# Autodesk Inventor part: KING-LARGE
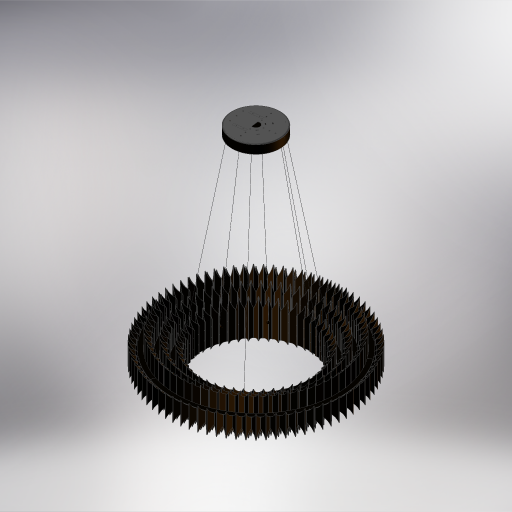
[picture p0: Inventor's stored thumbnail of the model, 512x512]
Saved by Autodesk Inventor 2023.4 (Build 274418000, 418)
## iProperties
Created: 2024-05
Part Number: KING-LARGE
Material: Generic
Document SubType Name: Modeling
Designer: JM
Density: 1 g/cm^3
Appearance: Default
Author: JM
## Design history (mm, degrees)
derived "KING-LARGE-0001-CUSTOMER.iam"
body "Solid1"
node "KINX-0008 - Ring size 4.iam:1::KINX0008.1 - Ring size 4.ipt:"
node "KINX-0020 - Ring size 5.iam:1::KINX-0020.1 - Ring size 5.ipt"
body "Solid2"
node "KINX-0021 - Ring size 6.iam:1::KINX-0021.1 - Ring size 6.ipt"
body "Solid3"
node "KINX-0022 - Ring top cover - size 5 - 959mm dia.ipt:1"
body "Solid4"
node "KINX-0023 - Ring top cover - size 6 - 1107mm dia.ipt:1"
body "Solid5"
node "KINX-0011 - Ring top cover - size 4 - 811mm dia.ipt:1"
body "Solid6"
node "KINX-0023 - Ring top cover - size 6 - 1107mm dia.ipt:2"
body "Solid7"
node "KINX-0022 - Ring top cover - size 5 - 959mm dia.ipt:2"
body "Solid8"
node "KINX-0011 - Ring top cover - size 4 - 811mm dia.ipt:2"
body "Solid9"
node "KINX-0023 - Ring top cover - size 6 - 1107mm dia.ipt:3"
body "Solid10"
node "KINX-0022 - Ring top cover - size 5 - 959mm dia.ipt:3"
body "Solid11"
node "KINX-0011 - Ring top cover - size 4 - 811mm dia.ipt:3"
body "Solid12"
node "KINX-0023 - Ring top cover - size 6 - 1107mm dia.ipt:4"
body "Solid13"
node "KINX-0022 - Ring top cover - size 5 - 959mm dia.ipt:4"
body "Solid14"
node "KINX-0011 - Ring top cover - size 4 - 811mm dia.ipt:4"
body "Solid15"
node "KINX-0023 - Ring top cover - size 6 - 1107mm dia.ipt:5"
body "Solid16"
node "KINX-0022 - Ring top cover - size 5 - 959mm dia.ipt:5"
body "Solid17"
node "KINX-0011 - Ring top cover - size 4 - 811mm dia.ipt:5"
body "Solid18"
node "KINX-0005 (KNG-UNILF-03) - Short outer leaves - CUSTOMERCAD."
body "Solid19"
node "KINX-0003 (KNG-UNILF-01) - Middle leaves - CUSTOMERCAD.ipt:1"
body "Solid20"
node "KINX-0001 (KNG-UNILF-02) - Inner leaves - CUSTOMERCAD.ipt:1"
body "Solid21"
node "KINX-0005 (KNG-UNILF-03) - Short outer leaves - CUSTOMERCAD."
body "Solid22"
node "KINX-0005 (KNG-UNILF-03) - Short outer leaves - CUSTOMERCAD."
body "Solid23"
node "KINX-0005 (KNG-UNILF-03) - Short outer leaves - CUSTOMERCAD."
body "Solid24"
node "KINX-0005 (KNG-UNILF-03) - Short outer leaves - CUSTOMERCAD."
body "Solid25"
node "KINX-0005 (KNG-UNILF-03) - Short outer leaves - CUSTOMERCAD."
body "Solid26"
node "KINX-0005 (KNG-UNILF-03) - Short outer leaves - CUSTOMERCAD."
body "Solid27"
node "KINX-0005 (KNG-UNILF-03) - Short outer leaves - CUSTOMERCAD."
body "Solid28"
node "KINX-0005 (KNG-UNILF-03) - Short outer leaves - CUSTOMERCAD."
body "Solid29"
node "KINX-0005 (KNG-UNILF-03) - Short outer leaves - CUSTOMERCAD."
body "Solid30"
node "KINX-0005 (KNG-UNILF-03) - Short outer leaves - CUSTOMERCAD."
body "Solid31"
node "KINX-0005 (KNG-UNILF-03) - Short outer leaves - CUSTOMERCAD."
body "Solid32"
node "KINX-0005 (KNG-UNILF-03) - Short outer leaves - CUSTOMERCAD."
body "Solid33"
node "KINX-0005 (KNG-UNILF-03) - Short outer leaves - CUSTOMERCAD."
body "Solid34"
node "KINX-0005 (KNG-UNILF-03) - Short outer leaves - CUSTOMERCAD."
body "Solid35"
node "KINX-0005 (KNG-UNILF-03) - Short outer leaves - CUSTOMERCAD."
body "Solid36"
node "KINX-0005 (KNG-UNILF-03) - Short outer leaves - CUSTOMERCAD."
body "Solid37"
node "KINX-0005 (KNG-UNILF-03) - Short outer leaves - CUSTOMERCAD."
body "Solid38"
node "KINX-0005 (KNG-UNILF-03) - Short outer leaves - CUSTOMERCAD."
body "Solid39"
node "KINX-0005 (KNG-UNILF-03) - Short outer leaves - CUSTOMERCAD."
body "Solid40"
node "KINX-0005 (KNG-UNILF-03) - Short outer leaves - CUSTOMERCAD."
body "Solid41"
node "KINX-0005 (KNG-UNILF-03) - Short outer leaves - CUSTOMERCAD."
body "Solid42"
node "KINX-0005 (KNG-UNILF-03) - Short outer leaves - CUSTOMERCAD."
body "Solid43"
node "KINX-0005 (KNG-UNILF-03) - Short outer leaves - CUSTOMERCAD."
body "Solid44"
node "KINX-0005 (KNG-UNILF-03) - Short outer leaves - CUSTOMERCAD."
body "Solid45"
node "KINX-0005 (KNG-UNILF-03) - Short outer leaves - CUSTOMERCAD."
body "Solid46"
node "KINX-0005 (KNG-UNILF-03) - Short outer leaves - CUSTOMERCAD."
body "Solid47"
node "KINX-0005 (KNG-UNILF-03) - Short outer leaves - CUSTOMERCAD."
body "Solid48"
node "KINX-0005 (KNG-UNILF-03) - Short outer leaves - CUSTOMERCAD."
body "Solid49"
node "KINX-0005 (KNG-UNILF-03) - Short outer leaves - CUSTOMERCAD."
body "Solid50"
node "KINX-0005 (KNG-UNILF-03) - Short outer leaves - CUSTOMERCAD."
body "Solid51"
node "KINX-0005 (KNG-UNILF-03) - Short outer leaves - CUSTOMERCAD."
body "Solid52"
node "KINX-0005 (KNG-UNILF-03) - Short outer leaves - CUSTOMERCAD."
body "Solid53"
node "KINX-0005 (KNG-UNILF-03) - Short outer leaves - CUSTOMERCAD."
body "Solid54"
node "KINX-0005 (KNG-UNILF-03) - Short outer leaves - CUSTOMERCAD."
body "Solid55"
node "KINX-0005 (KNG-UNILF-03) - Short outer leaves - CUSTOMERCAD."
body "Solid56"
node "KINX-0005 (KNG-UNILF-03) - Short outer leaves - CUSTOMERCAD."
body "Solid57"
node "KINX-0005 (KNG-UNILF-03) - Short outer leaves - CUSTOMERCAD."
body "Solid58"
node "KINX-0005 (KNG-UNILF-03) - Short outer leaves - CUSTOMERCAD."
body "Solid59"
node "KINX-0005 (KNG-UNILF-03) - Short outer leaves - CUSTOMERCAD."
body "Solid60"
node "KINX-0005 (KNG-UNILF-03) - Short outer leaves - CUSTOMERCAD."
body "Solid61"
node "KINX-0005 (KNG-UNILF-03) - Short outer leaves - CUSTOMERCAD."
body "Solid62"
node "KINX-0005 (KNG-UNILF-03) - Short outer leaves - CUSTOMERCAD."
body "Solid63"
node "KINX-0005 (KNG-UNILF-03) - Short outer leaves - CUSTOMERCAD."
body "Solid64"
node "KINX-0005 (KNG-UNILF-03) - Short outer leaves - CUSTOMERCAD."
body "Solid65"
node "KINX-0005 (KNG-UNILF-03) - Short outer leaves - CUSTOMERCAD."
body "Solid66"
node "KINX-0005 (KNG-UNILF-03) - Short outer leaves - CUSTOMERCAD."
body "Solid67"
node "KINX-0005 (KNG-UNILF-03) - Short outer leaves - CUSTOMERCAD."
body "Solid68"
node "KINX-0005 (KNG-UNILF-03) - Short outer leaves - CUSTOMERCAD."
body "Solid69"
node "KINX-0005 (KNG-UNILF-03) - Short outer leaves - CUSTOMERCAD."
body "Solid70"
node "KINX-0005 (KNG-UNILF-03) - Short outer leaves - CUSTOMERCAD."
body "Solid71"
node "KINX-0005 (KNG-UNILF-03) - Short outer leaves - CUSTOMERCAD."
body "Solid72"
node "KINX-0005 (KNG-UNILF-03) - Short outer leaves - CUSTOMERCAD."
body "Solid73"
node "KINX-0005 (KNG-UNILF-03) - Short outer leaves - CUSTOMERCAD."
body "Solid74"
node "KINX-0005 (KNG-UNILF-03) - Short outer leaves - CUSTOMERCAD."
body "Solid75"
node "KINX-0005 (KNG-UNILF-03) - Short outer leaves - CUSTOMERCAD."
body "Solid76"
node "KINX-0005 (KNG-UNILF-03) - Short outer leaves - CUSTOMERCAD."
body "Solid77"
node "KINX-0005 (KNG-UNILF-03) - Short outer leaves - CUSTOMERCAD."
body "Solid78"
node "KINX-0005 (KNG-UNILF-03) - Short outer leaves - CUSTOMERCAD."
body "Solid79"
node "KINX-0005 (KNG-UNILF-03) - Short outer leaves - CUSTOMERCAD."
body "Solid80"
node "KINX-0005 (KNG-UNILF-03) - Short outer leaves - CUSTOMERCAD."
body "Solid81"
node "KINX-0005 (KNG-UNILF-03) - Short outer leaves - CUSTOMERCAD."
body "Solid82"
node "KINX-0005 (KNG-UNILF-03) - Short outer leaves - CUSTOMERCAD."
body "Solid83"
node "KINX-0005 (KNG-UNILF-03) - Short outer leaves - CUSTOMERCAD."
body "Solid84"
node "KINX-0005 (KNG-UNILF-03) - Short outer leaves - CUSTOMERCAD."
body "Solid85"
node "KINX-0005 (KNG-UNILF-03) - Short outer leaves - CUSTOMERCAD."
body "Solid86"
node "KINX-0005 (KNG-UNILF-03) - Short outer leaves - CUSTOMERCAD."
body "Solid87"
node "KINX-0005 (KNG-UNILF-03) - Short outer leaves - CUSTOMERCAD."
body "Solid88"
node "KINX-0005 (KNG-UNILF-03) - Short outer leaves - CUSTOMERCAD."
body "Solid89"
node "KINX-0005 (KNG-UNILF-03) - Short outer leaves - CUSTOMERCAD."
body "Solid90"
node "KINX-0005 (KNG-UNILF-03) - Short outer leaves - CUSTOMERCAD."
body "Solid91"
node "KINX-0005 (KNG-UNILF-03) - Short outer leaves - CUSTOMERCAD."
body "Solid92"
node "KINX-0005 (KNG-UNILF-03) - Short outer leaves - CUSTOMERCAD."
body "Solid93"
node "KINX-0005 (KNG-UNILF-03) - Short outer leaves - CUSTOMERCAD."
body "Solid94"
node "KINX-0005 (KNG-UNILF-03) - Short outer leaves - CUSTOMERCAD."
body "Solid95"
node "KINX-0005 (KNG-UNILF-03) - Short outer leaves - CUSTOMERCAD."
body "Solid96"
node "KINX-0005 (KNG-UNILF-03) - Short outer leaves - CUSTOMERCAD."
body "Solid97"
node "KINX-0005 (KNG-UNILF-03) - Short outer leaves - CUSTOMERCAD."
body "Solid98"
node "KINX-0005 (KNG-UNILF-03) - Short outer leaves - CUSTOMERCAD."
body "Solid99"
node "KINX-0005 (KNG-UNILF-03) - Short outer leaves - CUSTOMERCAD."
body "Solid100"
node "KINX-0003 (KNG-UNILF-01) - Middle leaves - CUSTOMERCAD.ipt:2"
body "Solid101"
node "KINX-0003 (KNG-UNILF-01) - Middle leaves - CUSTOMERCAD.ipt:3"
body "Solid102"
node "KINX-0003 (KNG-UNILF-01) - Middle leaves - CUSTOMERCAD.ipt:4"
body "Solid103"
node "KINX-0003 (KNG-UNILF-01) - Middle leaves - CUSTOMERCAD.ipt:5"
body "Solid104"
node "KINX-0003 (KNG-UNILF-01) - Middle leaves - CUSTOMERCAD.ipt:6"
body "Solid105"
node "KINX-0003 (KNG-UNILF-01) - Middle leaves - CUSTOMERCAD.ipt:7"
body "Solid106"
node "KINX-0003 (KNG-UNILF-01) - Middle leaves - CUSTOMERCAD.ipt:8"
body "Solid107"
node "KINX-0003 (KNG-UNILF-01) - Middle leaves - CUSTOMERCAD.ipt:9"
body "Solid108"
node "KINX-0003 (KNG-UNILF-01) - Middle leaves - CUSTOMERCAD.ipt:1"
body "Solid109"
node "KINX-0003 (KNG-UNILF-01) - Middle leaves - CUSTOMERCAD.ipt:1"
body "Solid110"
node "KINX-0003 (KNG-UNILF-01) - Middle leaves - CUSTOMERCAD.ipt:1"
body "Solid111"
node "KINX-0003 (KNG-UNILF-01) - Middle leaves - CUSTOMERCAD.ipt:1"
body "Solid112"
node "KINX-0003 (KNG-UNILF-01) - Middle leaves - CUSTOMERCAD.ipt:1"
body "Solid113"
node "KINX-0003 (KNG-UNILF-01) - Middle leaves - CUSTOMERCAD.ipt:1"
body "Solid114"
node "KINX-0003 (KNG-UNILF-01) - Middle leaves - CUSTOMERCAD.ipt:1"
body "Solid115"
node "KINX-0003 (KNG-UNILF-01) - Middle leaves - CUSTOMERCAD.ipt:1"
body "Solid116"
node "KINX-0003 (KNG-UNILF-01) - Middle leaves - CUSTOMERCAD.ipt:1"
body "Solid117"
node "KINX-0003 (KNG-UNILF-01) - Middle leaves - CUSTOMERCAD.ipt:1"
body "Solid118"
node "KINX-0003 (KNG-UNILF-01) - Middle leaves - CUSTOMERCAD.ipt:2"
body "Solid119"
node "KINX-0003 (KNG-UNILF-01) - Middle leaves - CUSTOMERCAD.ipt:2"
body "Solid120"
node "KINX-0003 (KNG-UNILF-01) - Middle leaves - CUSTOMERCAD.ipt:2"
body "Solid121"
node "KINX-0003 (KNG-UNILF-01) - Middle leaves - CUSTOMERCAD.ipt:2"
body "Solid122"
node "KINX-0003 (KNG-UNILF-01) - Middle leaves - CUSTOMERCAD.ipt:2"
body "Solid123"
node "KINX-0003 (KNG-UNILF-01) - Middle leaves - CUSTOMERCAD.ipt:2"
body "Solid124"
node "KINX-0003 (KNG-UNILF-01) - Middle leaves - CUSTOMERCAD.ipt:2"
body "Solid125"
node "KINX-0003 (KNG-UNILF-01) - Middle leaves - CUSTOMERCAD.ipt:2"
body "Solid126"
node "KINX-0003 (KNG-UNILF-01) - Middle leaves - CUSTOMERCAD.ipt:2"
body "Solid127"
node "KINX-0003 (KNG-UNILF-01) - Middle leaves - CUSTOMERCAD.ipt:2"
body "Solid128"
node "KINX-0003 (KNG-UNILF-01) - Middle leaves - CUSTOMERCAD.ipt:3"
body "Solid129"
node "KINX-0003 (KNG-UNILF-01) - Middle leaves - CUSTOMERCAD.ipt:3"
body "Solid130"
node "KINX-0003 (KNG-UNILF-01) - Middle leaves - CUSTOMERCAD.ipt:3"
body "Solid131"
node "KINX-0003 (KNG-UNILF-01) - Middle leaves - CUSTOMERCAD.ipt:3"
body "Solid132"
node "KINX-0003 (KNG-UNILF-01) - Middle leaves - CUSTOMERCAD.ipt:3"
body "Solid133"
node "KINX-0003 (KNG-UNILF-01) - Middle leaves - CUSTOMERCAD.ipt:3"
body "Solid134"
node "KINX-0003 (KNG-UNILF-01) - Middle leaves - CUSTOMERCAD.ipt:3"
body "Solid135"
node "KINX-0003 (KNG-UNILF-01) - Middle leaves - CUSTOMERCAD.ipt:3"
body "Solid136"
node "KINX-0003 (KNG-UNILF-01) - Middle leaves - CUSTOMERCAD.ipt:3"
body "Solid137"
node "KINX-0003 (KNG-UNILF-01) - Middle leaves - CUSTOMERCAD.ipt:3"
body "Solid138"
node "KINX-0003 (KNG-UNILF-01) - Middle leaves - CUSTOMERCAD.ipt:4"
body "Solid139"
node "KINX-0003 (KNG-UNILF-01) - Middle leaves - CUSTOMERCAD.ipt:4"
body "Solid140"
node "KINX-0003 (KNG-UNILF-01) - Middle leaves - CUSTOMERCAD.ipt:4"
body "Solid141"
node "KINX-0003 (KNG-UNILF-01) - Middle leaves - CUSTOMERCAD.ipt:4"
body "Solid142"
node "KINX-0003 (KNG-UNILF-01) - Middle leaves - CUSTOMERCAD.ipt:4"
body "Solid143"
node "KINX-0003 (KNG-UNILF-01) - Middle leaves - CUSTOMERCAD.ipt:4"
body "Solid144"
node "KINX-0003 (KNG-UNILF-01) - Middle leaves - CUSTOMERCAD.ipt:4"
body "Solid145"
node "KINX-0003 (KNG-UNILF-01) - Middle leaves - CUSTOMERCAD.ipt:4"
body "Solid146"
node "KINX-0003 (KNG-UNILF-01) - Middle leaves - CUSTOMERCAD.ipt:4"
body "Solid147"
node "KINX-0003 (KNG-UNILF-01) - Middle leaves - CUSTOMERCAD.ipt:4"
body "Solid148"
node "KINX-0003 (KNG-UNILF-01) - Middle leaves - CUSTOMERCAD.ipt:5"
body "Solid149"
node "KINX-0003 (KNG-UNILF-01) - Middle leaves - CUSTOMERCAD.ipt:5"
body "Solid150"
node "KINX-0003 (KNG-UNILF-01) - Middle leaves - CUSTOMERCAD.ipt:5"
body "Solid151"
node "KINX-0003 (KNG-UNILF-01) - Middle leaves - CUSTOMERCAD.ipt:5"
body "Solid152"
node "KINX-0003 (KNG-UNILF-01) - Middle leaves - CUSTOMERCAD.ipt:5"
body "Solid153"
node "KINX-0003 (KNG-UNILF-01) - Middle leaves - CUSTOMERCAD.ipt:5"
body "Solid154"
node "KINX-0003 (KNG-UNILF-01) - Middle leaves - CUSTOMERCAD.ipt:5"
body "Solid155"
node "KINX-0003 (KNG-UNILF-01) - Middle leaves - CUSTOMERCAD.ipt:5"
body "Solid156"
node "KINX-0003 (KNG-UNILF-01) - Middle leaves - CUSTOMERCAD.ipt:5"
body "Solid157"
node "KINX-0003 (KNG-UNILF-01) - Middle leaves - CUSTOMERCAD.ipt:5"
body "Solid158"
node "KINX-0003 (KNG-UNILF-01) - Middle leaves - CUSTOMERCAD.ipt:6"
body "Solid159"
node "KINX-0003 (KNG-UNILF-01) - Middle leaves - CUSTOMERCAD.ipt:6"
body "Solid160"
node "KINX-0003 (KNG-UNILF-01) - Middle leaves - CUSTOMERCAD.ipt:6"
body "Solid161"
node "KINX-0003 (KNG-UNILF-01) - Middle leaves - CUSTOMERCAD.ipt:6"
body "Solid162"
node "KINX-0003 (KNG-UNILF-01) - Middle leaves - CUSTOMERCAD.ipt:6"
body "Solid163"
node "KINX-0003 (KNG-UNILF-01) - Middle leaves - CUSTOMERCAD.ipt:6"
body "Solid164"
node "KINX-0003 (KNG-UNILF-01) - Middle leaves - CUSTOMERCAD.ipt:6"
body "Solid165"
node "KINX-0003 (KNG-UNILF-01) - Middle leaves - CUSTOMERCAD.ipt:6"
body "Solid166"
node "KINX-0003 (KNG-UNILF-01) - Middle leaves - CUSTOMERCAD.ipt:6"
body "Solid167"
node "KINX-0003 (KNG-UNILF-01) - Middle leaves - CUSTOMERCAD.ipt:6"
body "Solid168"
node "KINX-0003 (KNG-UNILF-01) - Middle leaves - CUSTOMERCAD.ipt:7"
body "Solid169"
node "KINX-0003 (KNG-UNILF-01) - Middle leaves - CUSTOMERCAD INNER"
body "Solid170"
node "KINX-0003 (KNG-UNILF-01) - Middle leaves - CUSTOMERCAD INNER"
body "Solid171"
node "KINX-0003 (KNG-UNILF-01) - Middle leaves - CUSTOMERCAD INNER"
body "Solid172"
node "KINX-0003 (KNG-UNILF-01) - Middle leaves - CUSTOMERCAD INNER"
body "Solid173"
node "KINX-0003 (KNG-UNILF-01) - Middle leaves - CUSTOMERCAD INNER"
body "Solid174"
node "KINX-0003 (KNG-UNILF-01) - Middle leaves - CUSTOMERCAD INNER"
body "Solid175"
node "KINX-0003 (KNG-UNILF-01) - Middle leaves - CUSTOMERCAD INNER"
body "Solid176"
node "KINX-0003 (KNG-UNILF-01) - Middle leaves - CUSTOMERCAD INNER"
body "Solid177"
node "KINX-0003 (KNG-UNILF-01) - Middle leaves - CUSTOMERCAD INNER"
body "Solid178"
node "KINX-0003 (KNG-UNILF-01) - Middle leaves - CUSTOMERCAD INNER"
body "Solid179"
node "KINX-0003 (KNG-UNILF-01) - Middle leaves - CUSTOMERCAD INNER"
body "Solid180"
node "KINX-0003 (KNG-UNILF-01) - Middle leaves - CUSTOMERCAD INNER"
body "Solid181"
node "KINX-0003 (KNG-UNILF-01) - Middle leaves - CUSTOMERCAD INNER"
body "Solid182"
node "KINX-0003 (KNG-UNILF-01) - Middle leaves - CUSTOMERCAD INNER"
body "Solid183"
node "KINX-0003 (KNG-UNILF-01) - Middle leaves - CUSTOMERCAD INNER"
body "Solid184"
node "KINX-0003 (KNG-UNILF-01) - Middle leaves - CUSTOMERCAD INNER"
body "Solid185"
node "KINX-0003 (KNG-UNILF-01) - Middle leaves - CUSTOMERCAD INNER"
body "Solid186"
node "KINX-0003 (KNG-UNILF-01) - Middle leaves - CUSTOMERCAD INNER"
body "Solid187"
node "KINX-0003 (KNG-UNILF-01) - Middle leaves - CUSTOMERCAD INNER"
body "Solid188"
node "KINX-0003 (KNG-UNILF-01) - Middle leaves - CUSTOMERCAD INNER"
body "Solid189"
node "KINX-0003 (KNG-UNILF-01) - Middle leaves - CUSTOMERCAD INNER"
body "Solid190"
node "KINX-0003 (KNG-UNILF-01) - Middle leaves - CUSTOMERCAD INNER"
body "Solid191"
node "KINX-0003 (KNG-UNILF-01) - Middle leaves - CUSTOMERCAD INNER"
body "Solid192"
node "KINX-0003 (KNG-UNILF-01) - Middle leaves - CUSTOMERCAD INNER"
body "Solid193"
node "KINX-0003 (KNG-UNILF-01) - Middle leaves - CUSTOMERCAD INNER"
body "Solid194"
node "KINX-0003 (KNG-UNILF-01) - Middle leaves - CUSTOMERCAD INNER"
body "Solid195"
node "KINX-0003 (KNG-UNILF-01) - Middle leaves - CUSTOMERCAD INNER"
body "Solid196"
node "KINX-0003 (KNG-UNILF-01) - Middle leaves - CUSTOMERCAD INNER"
body "Solid197"
node "KINX-0003 (KNG-UNILF-01) - Middle leaves - CUSTOMERCAD INNER"
body "Solid198"
node "KINX-0003 (KNG-UNILF-01) - Middle leaves - CUSTOMERCAD INNER"
body "Solid199"
node "KINX-0003 (KNG-UNILF-01) - Middle leaves - CUSTOMERCAD INNER"
body "Solid200"
node "KINX-0003 (KNG-UNILF-01) - Middle leaves - CUSTOMERCAD INNER"
body "Solid201"
node "KINX-0003 (KNG-UNILF-01) - Middle leaves - CUSTOMERCAD INNER"
body "Solid202"
node "KINX-0003 (KNG-UNILF-01) - Middle leaves - CUSTOMERCAD INNER"
body "Solid203"
node "KINX-0003 (KNG-UNILF-01) - Middle leaves - CUSTOMERCAD INNER"
body "Solid204"
node "KINX-0003 (KNG-UNILF-01) - Middle leaves - CUSTOMERCAD INNER"
body "Solid205"
node "KINX-0003 (KNG-UNILF-01) - Middle leaves - CUSTOMERCAD INNER"
body "Solid206"
node "KINX-0003 (KNG-UNILF-01) - Middle leaves - CUSTOMERCAD INNER"
body "Solid207"
node "KINX-0003 (KNG-UNILF-01) - Middle leaves - CUSTOMERCAD INNER"
body "Solid208"
node "KINX-0003 (KNG-UNILF-01) - Middle leaves - CUSTOMERCAD INNER"
body "Solid209"
node "KINX-0003 (KNG-UNILF-01) - Middle leaves - CUSTOMERCAD INNER"
body "Solid210"
node "KINX-0003 (KNG-UNILF-01) - Middle leaves - CUSTOMERCAD INNER"
body "Solid211"
node "KINX-0003 (KNG-UNILF-01) - Middle leaves - CUSTOMERCAD INNER"
body "Solid212"
node "KINX-0003 (KNG-UNILF-01) - Middle leaves - CUSTOMERCAD INNER"
body "Solid213"
node "KINX-0003 (KNG-UNILF-01) - Middle leaves - CUSTOMERCAD INNER"
body "Solid214"
node "KINX-0003 (KNG-UNILF-01) - Middle leaves - CUSTOMERCAD INNER"
body "Solid215"
node "KINX-0003 (KNG-UNILF-01) - Middle leaves - CUSTOMERCAD INNER"
body "Solid216"
node "KINX-0003 (KNG-UNILF-01) - Middle leaves - CUSTOMERCAD INNER"
body "Solid217"
node "KINX-0003 (KNG-UNILF-01) - Middle leaves - CUSTOMERCAD INNER"
body "Solid218"
node "KINX-0003 (KNG-UNILF-01) - Middle leaves - CUSTOMERCAD INNER"
body "Solid219"
node "KINX-0003 (KNG-UNILF-01) - Middle leaves - CUSTOMERCAD INNER"
body "Solid220"
node "KINX-0003 (KNG-UNILF-01) - Middle leaves - CUSTOMERCAD INNER"
body "Solid221"
node "KINX-0003 (KNG-UNILF-01) - Middle leaves - CUSTOMERCAD INNER"
body "Solid222"
node "KINX-0003 (KNG-UNILF-01) - Middle leaves - CUSTOMERCAD INNER"
body "Solid223"
node "KINX-0003 (KNG-UNILF-01) - Middle leaves - CUSTOMERCAD INNER"
body "Solid224"
node "KINX-0003 (KNG-UNILF-01) - Middle leaves - CUSTOMERCAD INNER"
body "Solid225"
node "KINX-0003 (KNG-UNILF-01) - Middle leaves - CUSTOMERCAD INNER"
body "Solid226"
node "KINX-0003 (KNG-UNILF-01) - Middle leaves - CUSTOMERCAD INNER"
body "Solid227"
node "KINX-0003 (KNG-UNILF-01) - Middle leaves - CUSTOMERCAD INNER"
body "Solid228"
node "KINX-0003 (KNG-UNILF-01) - Middle leaves - CUSTOMERCAD INNER"
body "Solid229"
node "KINX-0001 (KNG-UNILF-02) - Inner leaves - CUSTOMERCAD.ipt:2"
body "Solid230"
node "KINX-0001 (KNG-UNILF-02) - Inner leaves - CUSTOMERCAD.ipt:3"
body "Solid231"
node "KINX-0001 (KNG-UNILF-02) - Inner leaves - CUSTOMERCAD.ipt:4"
body "Solid232"
node "KINX-0001 (KNG-UNILF-02) - Inner leaves - CUSTOMERCAD.ipt:5"
body "Solid233"
node "KINX-0001 (KNG-UNILF-02) - Inner leaves - CUSTOMERCAD.ipt:6"
body "Solid234"
node "KINX-0001 (KNG-UNILF-02) - Inner leaves - CUSTOMERCAD.ipt:7"
body "Solid235"
node "KINX-0001 (KNG-UNILF-02) - Inner leaves - CUSTOMERCAD.ipt:8"
body "Solid236"
node "KINX-0001 (KNG-UNILF-02) - Inner leaves - CUSTOMERCAD.ipt:9"
body "Solid237"
node "KINX-0001 (KNG-UNILF-02) - Inner leaves - CUSTOMERCAD.ipt:10"
body "Solid238"
node "KINX-0001 (KNG-UNILF-02) - Inner leaves - CUSTOMERCAD.ipt:11"
body "Solid239"
node "KINX-0001 (KNG-UNILF-02) - Inner leaves - CUSTOMERCAD.ipt:12"
body "Solid240"
node "KINX-0001 (KNG-UNILF-02) - Inner leaves - CUSTOMERCAD.ipt:13"
body "Solid241"
node "KINX-0001 (KNG-UNILF-02) - Inner leaves - CUSTOMERCAD.ipt:14"
body "Solid242"
node "KINX-0001 (KNG-UNILF-02) - Inner leaves - CUSTOMERCAD.ipt:15"
body "Solid243"
node "KINX-0001 (KNG-UNILF-02) - Inner leaves - CUSTOMERCAD.ipt:16"
body "Solid244"
node "KINX-0001 (KNG-UNILF-02) - Inner leaves - CUSTOMERCAD.ipt:17"
body "Solid245"
node "KINX-0001 (KNG-UNILF-02) - Inner leaves - CUSTOMERCAD.ipt:18"
body "Solid246"
node "KINX-0001 (KNG-UNILF-02) - Inner leaves - CUSTOMERCAD.ipt:19"
body "Solid247"
node "KINX-0001 (KNG-UNILF-02) - Inner leaves - CUSTOMERCAD.ipt:20"
body "Solid248"
node "KINX-0001 (KNG-UNILF-02) - Inner leaves - CUSTOMERCAD.ipt:21"
body "Solid249"
node "KINX-0001 (KNG-UNILF-02) - Inner leaves - CUSTOMERCAD.ipt:22"
body "Solid250"
node "KINX-0001 (KNG-UNILF-02) - Inner leaves - CUSTOMERCAD.ipt:23"
body "Solid251"
node "KINX-0001 (KNG-UNILF-02) - Inner leaves - CUSTOMERCAD.ipt:24"
body "Solid252"
node "KINX-0001 (KNG-UNILF-02) - Inner leaves - CUSTOMERCAD.ipt:25"
body "Solid253"
node "KINX-0001 (KNG-UNILF-02) - Inner leaves - CUSTOMERCAD.ipt:26"
body "Solid254"
node "KINX-0001 (KNG-UNILF-02) - Inner leaves - CUSTOMERCAD.ipt:27"
body "Solid255"
node "KINX-0001 (KNG-UNILF-02) - Inner leaves - CUSTOMERCAD.ipt:28"
body "Solid256"
node "KINX-0001 (KNG-UNILF-02) - Inner leaves - CUSTOMERCAD.ipt:29"
body "Solid257"
node "KINX-0001 (KNG-UNILF-02) - Inner leaves - CUSTOMERCAD.ipt:30"
body "Solid258"
node "KINX-0001 (KNG-UNILF-02) - Inner leaves - CUSTOMERCAD.ipt:31"
body "Solid259"
node "KINX-0001 (KNG-UNILF-02) - Inner leaves - CUSTOMERCAD.ipt:32"
body "Solid260"
node "KINX-0001 (KNG-UNILF-02) - Inner leaves - CUSTOMERCAD.ipt:33"
body "Solid261"
node "KINX-0001 (KNG-UNILF-02) - Inner leaves - CUSTOMERCAD.ipt:34"
body "Solid262"
node "KINX-0001 (KNG-UNILF-02) - Inner leaves - CUSTOMERCAD.ipt:35"
body "Solid263"
node "KINX-0001 (KNG-UNILF-02) - Inner leaves - CUSTOMERCAD.ipt:36"
body "Solid264"
node "KINX-0001 (KNG-UNILF-02) - Inner leaves - CUSTOMERCAD.ipt:37"
body "Solid265"
node "KINX-0001 (KNG-UNILF-02) - Inner leaves - CUSTOMERCAD.ipt:38"
body "Solid266"
node "KINX-0001 (KNG-UNILF-02) - Inner leaves - CUSTOMERCAD.ipt:39"
body "Solid267"
node "KINX-0001 (KNG-UNILF-02) - Inner leaves - CUSTOMERCAD.ipt:40"
body "Solid268"
node "KINX-0001 (KNG-UNILF-02) - Inner leaves - CUSTOMERCAD.ipt:41"
body "Solid269"
node "KINX-0001 (KNG-UNILF-02) - Inner leaves - CUSTOMERCAD.ipt:42"
body "Solid270"
node "KINX-0001 (KNG-UNILF-02) - Inner leaves - CUSTOMERCAD.ipt:43"
body "Solid271"
node "KINX-0001 (KNG-UNILF-02) - Inner leaves - CUSTOMERCAD.ipt:44"
body "Solid272"
node "KINX-0001 (KNG-UNILF-02) - Inner leaves - CUSTOMERCAD.ipt:45"
body "Solid273"
node "KINX-0001 (KNG-UNILF-02) - Inner leaves - CUSTOMERCAD.ipt:46"
body "Solid274"
node "KINX-0001 (KNG-UNILF-02) - Inner leaves - CUSTOMERCAD.ipt:47"
body "Solid275"
node "KINX-0001 (KNG-UNILF-02) - Inner leaves - CUSTOMERCAD.ipt:48"
body "Solid276"
node "KINX-0001 (KNG-UNILF-02) - Inner leaves - CUSTOMERCAD.ipt:49"
body "Solid277"
node "KINX-0001 (KNG-UNILF-02) - Inner leaves - CUSTOMERCAD.ipt:50"
body "Solid278"
node "finial-15mm.ipt:1"
body "Solid279"
node "turned-screw-cover.ipt:1"
body "Solid280"
node "turned-screw-cover.ipt:2"
body "Solid281"
node "finial-15mm.ipt:2"
body "Solid282"
node "turned-screw-cover.ipt:3"
body "Solid283"
node "finial-15mm.ipt:3"
body "Solid284"
node "turned-screw-cover.ipt:4"
body "Solid285"
node "finial-15mm.ipt:4"
body "Solid286"
node "turned-screw-cover.ipt:5"
body "Solid287"
node "finial-15mm.ipt:5"
body "Solid288"
node "turned-screw-cover.ipt:6"
body "Solid289"
node "finial-15mm.ipt:6"
body "Solid290"
node "turned-screw-cover.ipt:7"
body "Solid291"
node "finial-15mm.ipt:7"
body "Solid292"
node "turned-screw-cover.ipt:8"
body "Solid293"
node "finial-15mm.ipt:8"
body "Solid294"
node "turned-screw-cover.ipt:9"
body "Solid295"
node "finial-15mm.ipt:9"
body "Solid296"
node "turned-screw-cover.ipt:10"
body "Solid297"
node "finial-15mm.ipt:10"
body "Solid298"
body "Solid299"
node "KINX-AS09 - Ceiling Rose - CUSTOMERCAD.iam:1::tensile-grip-0"
body "Solid300"
node "KINX-AS09 - Ceiling Rose - CUSTOMERCAD.iam:1::tensile-grip-0"
body "Solid301"
node "KINX-AS09 - Ceiling Rose - CUSTOMERCAD.iam:1::tensile-grip-0"
body "Solid302"
node "KINX-AS09 - Ceiling Rose - CUSTOMERCAD.iam:1::tensile-grip-0"
body "Solid303"
node "KINX-AS09 - Ceiling Rose - CUSTOMERCAD.iam:1::tensile-grip-0"
body "Solid304"
body "Solid305"
body "Solid306"
body "Solid307"
body "Solid308"
body "Solid309"
node "Tensile-cable-CUSTOMERCAD.ipt:1"
body "Solid310"
node "Tensile-cable-CUSTOMERCAD.ipt:2"
body "Solid311"
node "Tensile-cable-CUSTOMERCAD.ipt:3"
body "Solid312"
node "Tensile-cable-CUSTOMERCAD.ipt:5"
body "Solid313"
node "Tensile-cable-CUSTOMERCAD.ipt:7"
body "Solid314"
node "Tensile-cable-CUSTOMERCAD.ipt:9"
body "Solid315"
node "Tensile-cable-CUSTOMERCAD.ipt:10"
body "Solid316"
